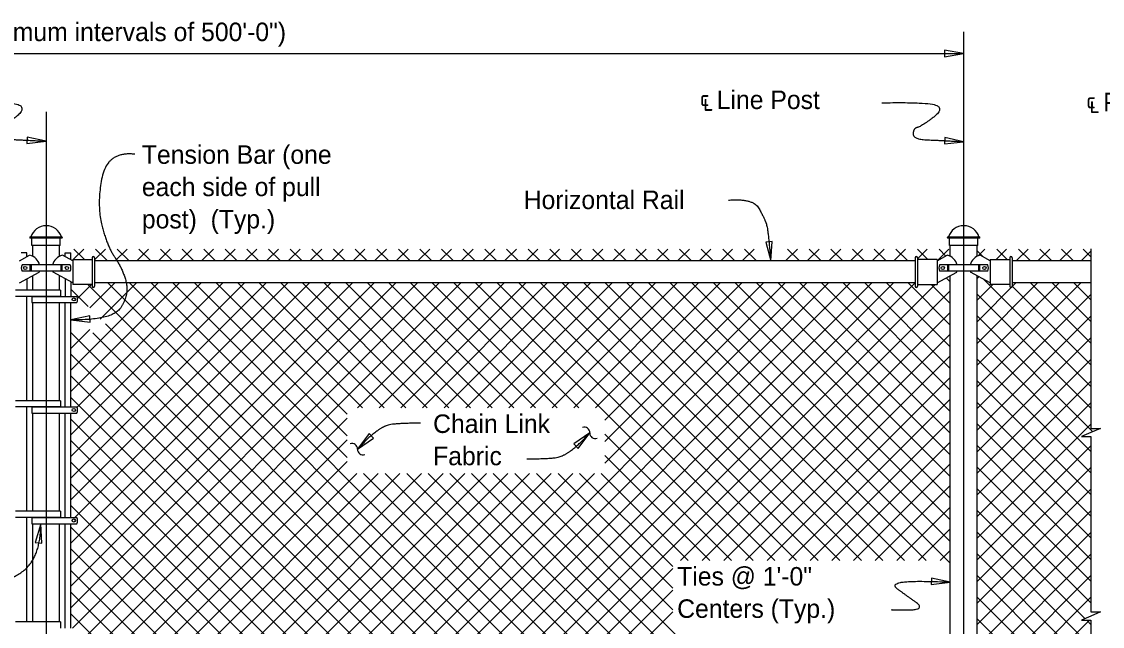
# Model space of a CAD drawing. Extents: x 0.4 to 38.5, y 1.2 to 25.4.
# Drawn here: x 11.81 to 23.59, y 18.85 to 25.44 of the extents above; entities that cross this region are included whole.
import ezdxf

# ---------------------------------------------------------------- set-up
doc = ezdxf.new("R2010")
doc.units = 0
for name, color, linetype in [('CL_Major', 7, 'Continuous'), ('Dimension', 7, 'Continuous'), ('Miscellaneous', 7, 'Continuous'), ('SteelMisc', 7, 'Continuous'), ('TextStructures', 7, 'Continuous')]:
    doc.layers.add(name, color=color, linetype=linetype)

msp = doc.modelspace()

# ---------------------------------------------------------------- linework, layer by layer
at = {"layer": 'CL_Major'}
for p, q in [((22.075, 25.325), (22.075, 16.544)), ((12.075, 24.454), (12.075, 16.544))]:
    msp.add_line(p, q, dxfattribs=at)
at = {"layer": 'Dimension'}
msp.add_line((2.075, 25.088), (22.075, 25.088), dxfattribs=at)
for points in [[(22.075, 25.088), (21.867, 25.124), (21.867, 25.053)], [(12.075, 24.132), (11.869, 24.178), (11.865, 24.108)], [(22.075, 24.127), (21.869, 24.174), (21.865, 24.103)], [(19.972, 22.827), (19.988, 23.038), (19.918, 23.031)], [(12.346, 22.187), (12.555, 22.16), (12.553, 22.23)], [(15.469, 20.777), (15.644, 20.895), (15.595, 20.946)], [(18.001, 20.953), (17.825, 20.835), (17.874, 20.784)], [(12.018, 19.964), (11.957, 19.761), (12.027, 19.753)], [(21.929, 19.328), (21.723, 19.372), (21.72, 19.302)]]:
    msp.add_lwpolyline(points, close=True, dxfattribs=at)
for points in [[(23.462, 22.959), (23.462, 21.003), (23.565, 21.003), (23.462, 20.958), (23.359, 20.913), (23.462, 20.913), (23.462, 20.019)], [(23.462, 20.019), (23.462, 19.002), (23.565, 19.002), (23.462, 18.957), (23.359, 18.912), (23.462, 18.912), (23.462, 16.957)]]:
    msp.add_lwpolyline(points, dxfattribs=at)
for centre, start, end in [((17.941, 20.956), 357.7178, 109.445), ((18.06, 20.951), 177.7178, 289.445), ((15.409, 20.779), 357.7178, 109.445), ((15.529, 20.774), 177.7178, 289.445)]:
    msp.add_arc(centre, 0.0596, start, end, dxfattribs=at)
for points in [[(11.185, 24.556), (11.731, 24.565), (11.854, 24.476), (11.609, 24.295), (11.525, 24.277), (11.525, 24.159), (11.803, 24.147), (12.075, 24.132)], [(21.185, 24.551), (21.731, 24.561), (21.854, 24.472), (21.61, 24.291), (21.525, 24.272), (21.525, 24.154), (21.803, 24.142), (22.075, 24.127)], [(13.041, 23.991), (12.741, 24.023), (12.626, 23.441), (12.741, 22.987), (12.905, 22.752), (12.984, 22.465), (12.797, 22.176), (12.346, 22.187)], [(19.511, 23.49), (19.782, 23.513), (19.908, 23.285), (19.945, 23.164), (19.972, 22.827)], [(16.154, 21.059), (15.864, 21.059), (15.727, 21.014), (15.54, 20.86), (15.502, 20.803)], [(17.315, 20.671), (17.606, 20.671), (17.742, 20.716), (17.929, 20.87), (17.968, 20.927)], [(10.387, 19.368), (10.783, 19.374), (11.232, 19.311), (11.594, 19.294), (12.015, 19.573), (12.018, 19.964)], [(21.297, 19.024), (21.253, 19.024), (21.673, 19.024), (21.423, 19.201), (21.286, 19.303), (21.496, 19.346), (21.929, 19.328)]]:
    msp.add_open_spline(points, degree=2, dxfattribs=at)
at = {"layer": 'Miscellaneous'}
for p, q in [((12.371, 22.843), (12.486, 22.957)), ((12.379, 22.957), (12.493, 22.843)), ((12.604, 22.84), (12.722, 22.957)), ((12.614, 22.957), (12.744, 22.827)), ((12.827, 22.827), (12.957, 22.957)), ((12.85, 22.957), (12.98, 22.827)), ((13.063, 22.827), (13.193, 22.957)), ((13.086, 22.957), (13.216, 22.827)), ((13.299, 22.827), (13.429, 22.957)), ((13.321, 22.957), (13.452, 22.827)), ((13.534, 22.827), (13.665, 22.957)), ((13.557, 22.957), (13.687, 22.827)), ((13.77, 22.827), (13.9, 22.957)), ((13.793, 22.957), (13.923, 22.827)), ((14.006, 22.827), (14.136, 22.957)), ((14.028, 22.957), (14.159, 22.827)), ((14.241, 22.827), (14.372, 22.957)), ((14.264, 22.957), (14.394, 22.827)), ((14.477, 22.827), (14.607, 22.957)), ((14.5, 22.957), (14.63, 22.827)), ((14.713, 22.827), (14.843, 22.957)), ((14.736, 22.957), (14.866, 22.827)), ((14.949, 22.827), (15.079, 22.957)), ((14.971, 22.957), (15.101, 22.827)), ((15.184, 22.827), (15.314, 22.957)), ((15.207, 22.957), (15.337, 22.827)), ((15.42, 22.827), (15.55, 22.957)), ((15.443, 22.957), (15.573, 22.827)), ((15.656, 22.827), (15.786, 22.957)), ((15.678, 22.957), (15.809, 22.827)), ((15.891, 22.827), (16.022, 22.957)), ((15.914, 22.957), (16.044, 22.827)), ((16.127, 22.827), (16.257, 22.957)), ((16.15, 22.957), (16.28, 22.827)), ((16.363, 22.827), (16.493, 22.957)), ((16.386, 22.957), (16.516, 22.827)), ((16.598, 22.827), (16.729, 22.957)), ((16.621, 22.957), (16.751, 22.827)), ((16.834, 22.827), (16.964, 22.957)), ((16.857, 22.957), (16.987, 22.827)), ((17.07, 22.827), (17.2, 22.957)), ((17.093, 22.957), (17.223, 22.827)), ((17.306, 22.827), (17.436, 22.957)), ((17.328, 22.957), (17.458, 22.827)), ((17.541, 22.827), (17.671, 22.957)), ((17.564, 22.957), (17.694, 22.827)), ((17.777, 22.827), (17.907, 22.957)), ((17.8, 22.957), (17.93, 22.827)), ((18.013, 22.827), (18.143, 22.957)), ((18.035, 22.957), (18.166, 22.827)), ((18.248, 22.827), (18.379, 22.957)), ((18.271, 22.957), (18.401, 22.827)), ((18.484, 22.827), (18.614, 22.957)), ((18.507, 22.957), (18.637, 22.827)), ((18.72, 22.827), (18.85, 22.957)), ((18.743, 22.957), (18.873, 22.827)), ((18.956, 22.827), (19.086, 22.957)), ((18.978, 22.957), (19.108, 22.827)), ((19.191, 22.827), (19.321, 22.957)), ((19.214, 22.957), (19.344, 22.827)), ((19.427, 22.827), (19.557, 22.957)), ((19.45, 22.957), (19.58, 22.827)), ((19.663, 22.827), (19.793, 22.957)), ((19.685, 22.957), (19.816, 22.827)), ((20.134, 22.827), (20.264, 22.957)), ((20.157, 22.957), (20.287, 22.827)), ((20.37, 22.827), (20.5, 22.957)), ((20.392, 22.957), (20.523, 22.827)), ((20.605, 22.827), (20.736, 22.957)), ((20.628, 22.957), (20.758, 22.827)), ((20.841, 22.827), (20.971, 22.957)), ((20.864, 22.957), (20.994, 22.827)), ((21.077, 22.827), (21.207, 22.957)), ((21.1, 22.957), (21.23, 22.827)), ((21.313, 22.827), (21.443, 22.957)), ((21.335, 22.957), (21.465, 22.827)), ((21.571, 22.957), (21.686, 22.843)), ((21.572, 22.851), (21.678, 22.957)), ((21.785, 22.829), (21.914, 22.957)), ((21.807, 22.957), (21.882, 22.881)), ((22.221, 22.936), (22.286, 22.871)), ((22.233, 22.883), (22.307, 22.957)), ((22.428, 22.843), (22.543, 22.957)), ((22.436, 22.957), (22.55, 22.843)), ((22.649, 22.827), (22.779, 22.957)), ((22.671, 22.957), (22.802, 22.827)), ((22.884, 22.827), (23.015, 22.957)), ((22.907, 22.957), (23.037, 22.827)), ((23.12, 22.827), (23.25, 22.957)), ((23.143, 22.957), (23.273, 22.827)), ((23.356, 22.827), (23.462, 22.933)), ((23.379, 22.957), (23.462, 22.874)), ((21.885, 22.643), (21.929, 22.599)), ((22.221, 22.635), (22.242, 22.656)), ((22.294, 22.627), (23.462, 21.46)), ((12.346, 19.517), (15.416, 22.588)), ((12.346, 19.046), (15.888, 22.588)), ((12.346, 20.932), (14.002, 22.588)), ((12.346, 20.46), (14.473, 22.588)), ((12.346, 21.403), (13.53, 22.588)), ((12.346, 19.282), (15.652, 22.588)), ((12.346, 19.753), (15.18, 22.588)), ((12.346, 20.224), (14.709, 22.588)), ((12.346, 20.696), (14.238, 22.588)), ((12.346, 18.339), (16.595, 22.588)), ((12.346, 18.574), (16.359, 22.588)), ((12.346, 21.639), (13.295, 22.588)), ((12.346, 22.519), (12.534, 22.33)), ((12.362, 18.826), (16.123, 22.588)), ((12.389, 20.031), (14.945, 22.588)), ((12.412, 21.233), (13.766, 22.588)), ((12.418, 22.418), (12.578, 22.577)), ((12.53, 22.57), (17.69, 17.41)), ((12.552, 22.317), (12.823, 22.588)), ((12.663, 22.192), (13.059, 22.588)), ((12.748, 22.588), (17.925, 17.41)), ((12.984, 22.588), (18.161, 17.41)), ((13.22, 22.588), (18.397, 17.41)), ((13.455, 22.588), (15.358, 20.685)), ((13.691, 22.588), (15.358, 20.921)), ((13.927, 22.588), (15.358, 21.157)), ((14.163, 22.588), (15.523, 21.227)), ((14.398, 22.588), (15.759, 21.227)), ((14.634, 22.588), (15.994, 21.227)), ((14.87, 22.588), (16.23, 21.227)), ((15.105, 22.588), (16.466, 21.227)), ((15.189, 17.41), (20.366, 22.588)), ((15.341, 22.588), (16.702, 21.227)), ((15.424, 17.41), (20.602, 22.588)), ((15.47, 21.227), (16.83, 22.588)), ((15.577, 22.588), (16.937, 21.227)), ((15.66, 17.41), (20.837, 22.588)), ((15.706, 21.227), (17.066, 22.588)), ((15.812, 22.588), (17.173, 21.227)), ((15.896, 17.41), (21.073, 22.588)), ((15.941, 21.227), (17.302, 22.588)), ((16.048, 22.588), (17.409, 21.227)), ((16.132, 17.41), (21.309, 22.588)), ((16.177, 21.227), (17.537, 22.588)), ((16.284, 22.588), (17.644, 21.227)), ((16.367, 17.41), (21.546, 22.589)), ((16.413, 21.227), (17.773, 22.588)), ((16.52, 22.588), (17.88, 21.227)), ((16.603, 17.41), (21.763, 22.57)), ((16.648, 21.227), (18.009, 22.588)), ((16.755, 22.588), (19.781, 19.562)), ((16.884, 21.227), (18.245, 22.588)), ((16.991, 22.588), (20.017, 19.562)), ((17.12, 21.227), (18.48, 22.588)), ((17.227, 22.588), (20.253, 19.562)), ((17.355, 21.227), (18.716, 22.588)), ((17.462, 22.588), (20.488, 19.562)), ((17.591, 21.227), (18.952, 22.588)), ((17.698, 22.588), (20.724, 19.562)), ((17.827, 21.227), (19.187, 22.588)), ((17.934, 22.588), (20.96, 19.562)), ((18.063, 21.227), (19.423, 22.588)), ((18.166, 21.094), (19.659, 22.588)), ((18.166, 20.623), (20.13, 22.588)), ((18.166, 20.859), (19.894, 22.588)), ((18.169, 22.588), (21.195, 19.562)), ((18.405, 22.588), (21.431, 19.562)), ((18.641, 22.588), (21.667, 19.562)), ((18.877, 22.588), (21.929, 19.535)), ((18.99, 19.562), (21.929, 22.501)), ((19.112, 22.588), (21.929, 19.771)), ((19.348, 22.588), (21.929, 20.006)), ((19.584, 22.588), (21.929, 20.242)), ((19.819, 22.588), (21.929, 20.478)), ((20.055, 22.588), (21.929, 20.713)), ((20.291, 22.588), (21.929, 20.949)), ((20.526, 22.588), (21.929, 21.185)), ((20.762, 22.588), (21.929, 21.42)), ((20.998, 22.588), (21.929, 21.656)), ((21.234, 22.588), (21.929, 21.892)), ((21.469, 22.588), (21.929, 22.128)), ((21.722, 22.57), (21.929, 22.363)), ((22.221, 21.456), (23.352, 22.588)), ((22.221, 21.692), (23.116, 22.588)), ((22.221, 22.164), (22.645, 22.588)), ((22.221, 22.399), (22.392, 22.57)), ((22.225, 21.932), (22.881, 22.588)), ((22.604, 22.553), (23.462, 21.695)), ((22.805, 22.588), (23.462, 21.931)), ((23.041, 22.588), (23.462, 22.167)), ((23.277, 22.588), (23.462, 22.402)), ((22.221, 22.465), (23.462, 21.224)), ((22.221, 21.221), (23.462, 22.462)), ((19.226, 19.562), (21.929, 22.265)), ((22.221, 22.229), (23.483, 20.967)), ((22.221, 20.985), (23.462, 22.226)), ((12.346, 21.874), (12.553, 22.081)), ((12.346, 22.047), (16.983, 17.41)), ((12.586, 22.043), (17.218, 17.41)), ((12.722, 22.142), (17.454, 17.41)), ((19.461, 19.562), (21.929, 22.03)), ((22.221, 21.994), (23.462, 20.752)), ((22.221, 20.749), (23.462, 21.99)), ((12.346, 21.811), (16.747, 17.41)), ((19.697, 19.562), (21.929, 21.794)), ((22.221, 21.758), (23.462, 20.517)), ((22.221, 20.514), (23.462, 21.755)), ((12.346, 21.576), (16.511, 17.41)), ((19.933, 19.562), (21.929, 21.558)), ((22.221, 21.522), (23.462, 20.281)), ((22.221, 20.278), (23.462, 21.519)), ((12.346, 21.34), (16.276, 17.41)), ((20.168, 19.562), (21.929, 21.322)), ((22.221, 21.286), (23.462, 20.045)), ((22.221, 20.042), (23.462, 21.283)), ((12.346, 18.103), (15.358, 21.115)), ((12.346, 21.104), (16.04, 17.41)), ((20.404, 19.562), (21.929, 21.087)), ((22.221, 21.051), (23.462, 19.81)), ((22.221, 19.807), (23.462, 21.048)), ((12.346, 17.867), (15.358, 20.879)), ((12.346, 20.869), (15.804, 17.41)), ((18.166, 20.941), (19.545, 19.562)), ((20.64, 19.562), (21.929, 20.851)), ((22.221, 20.815), (23.462, 19.574)), ((22.221, 19.571), (23.462, 20.812)), ((12.346, 17.632), (15.358, 20.643)), ((12.346, 20.633), (15.568, 17.41)), ((18.166, 20.706), (19.31, 19.562)), ((20.875, 19.562), (21.929, 20.615)), ((12.376, 17.426), (15.46, 20.51)), ((12.604, 17.419), (15.695, 20.51)), ((12.832, 17.41), (15.931, 20.51)), ((13.067, 17.41), (16.167, 20.51)), ((13.303, 17.41), (16.402, 20.51)), ((13.539, 17.41), (16.638, 20.51)), ((13.774, 17.41), (16.874, 20.51)), ((14.01, 17.41), (17.109, 20.51)), ((14.246, 17.41), (17.345, 20.51)), ((14.482, 17.41), (17.581, 20.51)), ((14.717, 17.41), (17.817, 20.51)), ((14.953, 17.41), (18.052, 20.51)), ((15.533, 20.51), (18.633, 17.41)), ((15.769, 20.51), (18.868, 17.41)), ((16.005, 20.51), (19.104, 17.41)), ((16.24, 20.51), (19.34, 17.41)), ((16.476, 20.51), (19.575, 17.41)), ((16.712, 20.51), (19.811, 17.41)), ((16.948, 20.51), (20.047, 17.41)), ((17.183, 20.51), (20.282, 17.41)), ((17.419, 20.51), (18.904, 19.024)), ((17.655, 20.51), (18.904, 19.26)), ((17.89, 20.51), (18.904, 19.496)), ((18.126, 20.51), (19.074, 19.562)), ((22.221, 20.579), (23.462, 19.338)), ((22.221, 19.335), (23.462, 20.576)), ((12.346, 20.397), (15.333, 17.41)), ((21.111, 19.562), (21.929, 20.38)), ((22.221, 20.344), (23.462, 19.103)), ((22.221, 19.099), (23.462, 20.341)), ((12.346, 20.162), (15.097, 17.41)), ((21.347, 19.562), (21.929, 20.144)), ((22.221, 20.108), (23.399, 18.929)), ((22.221, 18.864), (23.462, 20.105)), ((12.346, 19.926), (14.861, 17.41)), ((21.583, 19.562), (21.929, 19.908)), ((22.221, 19.872), (23.462, 18.631)), ((22.221, 18.628), (23.462, 19.869)), ((12.346, 19.69), (14.626, 17.41)), ((21.818, 19.562), (21.929, 19.673)), ((22.221, 19.637), (23.462, 18.395)), ((22.221, 18.392), (23.462, 19.633)), ((12.346, 19.454), (14.39, 17.41)), ((16.839, 17.41), (18.904, 19.476)), ((22.221, 19.401), (23.462, 18.16)), ((22.221, 18.157), (23.462, 19.398)), ((12.346, 19.219), (14.154, 17.41)), ((17.074, 17.41), (18.904, 19.24)), ((22.221, 19.165), (23.462, 17.924)), ((22.221, 17.921), (23.462, 19.162)), ((12.346, 18.983), (13.919, 17.41)), ((17.31, 17.41), (18.904, 19.005)), ((22.221, 18.929), (23.462, 17.688)), ((22.221, 17.685), (23.447, 18.912)), ((23.417, 18.912), (23.462, 18.867))]:
    msp.add_line(p, q, dxfattribs=at)
at = {"layer": 'SteelMisc'}
for p, q in [((11.903, 23.089), (12.247, 23.089)), ((21.903, 23.089), (22.247, 23.089)), ((12.247, 23.077), (11.903, 23.077)), ((11.921, 22.997), (11.921, 23.077)), ((12.229, 22.997), (11.921, 22.997)), ((11.929, 22.877), (11.929, 22.997)), ((12.221, 22.877), (12.221, 22.997)), ((12.229, 22.997), (12.229, 23.077)), ((22.247, 23.077), (21.903, 23.077)), ((21.921, 22.997), (21.921, 23.077)), ((22.229, 22.997), (21.921, 22.997)), ((21.929, 22.877), (21.929, 22.997)), ((22.221, 22.877), (22.221, 22.997)), ((22.229, 22.997), (22.229, 23.077)), ((11.785, 22.828), (11.896, 22.889)), ((11.867, 22.916), (11.804, 22.916)), ((11.867, 22.873), (11.867, 22.916)), ((12.365, 22.828), (12.254, 22.889)), ((12.283, 22.874), (12.283, 22.916)), ((12.283, 22.916), (12.346, 22.916)), ((12.346, 22.838), (12.346, 22.916)), ((12.578, 22.862), (12.578, 22.552)), ((12.604, 22.862), (12.604, 22.552)), ((21.546, 22.862), (21.546, 22.552)), ((21.572, 22.862), (21.572, 22.552)), ((21.785, 22.828), (21.896, 22.889)), ((22.365, 22.828), (22.254, 22.889)), ((22.578, 22.862), (22.578, 22.552)), ((22.604, 22.862), (22.604, 22.552)), ((12.337, 22.785), (11.813, 22.785)), ((11.895, 22.777), (11.918, 22.777)), ((11.895, 22.768), (11.918, 22.768)), ((11.895, 22.757), (11.918, 22.757)), ((11.895, 22.745), (11.918, 22.745)), ((11.895, 22.733), (11.918, 22.733)), ((12.255, 22.777), (12.232, 22.777)), ((12.255, 22.768), (12.232, 22.768)), ((12.255, 22.757), (12.232, 22.757)), ((12.255, 22.745), (12.232, 22.745)), ((12.255, 22.733), (12.232, 22.733)), ((12.365, 22.843), (12.365, 22.57)), ((12.365, 22.843), (12.578, 22.843)), ((21.546, 22.827), (12.604, 22.827)), ((21.785, 22.843), (21.572, 22.843)), ((21.785, 22.843), (21.785, 22.57)), ((22.337, 22.785), (21.813, 22.785)), ((21.895, 22.777), (21.918, 22.777)), ((21.895, 22.768), (21.918, 22.768)), ((21.895, 22.757), (21.918, 22.757)), ((21.895, 22.745), (21.918, 22.745)), ((21.895, 22.733), (21.918, 22.733)), ((22.255, 22.777), (22.232, 22.777)), ((22.255, 22.768), (22.232, 22.768)), ((22.255, 22.757), (22.232, 22.757)), ((22.255, 22.745), (22.232, 22.745)), ((22.255, 22.733), (22.232, 22.733)), ((22.365, 22.843), (22.365, 22.57)), ((22.365, 22.843), (22.578, 22.843)), ((23.462, 22.827), (22.604, 22.827)), ((11.785, 22.588), (11.999, 22.707)), ((12.337, 22.717), (11.813, 22.717)), ((11.867, 22.633), (11.867, 22.508)), ((11.895, 22.724), (11.918, 22.724)), ((11.929, 22.508), (11.929, 22.668)), ((12.365, 22.588), (12.151, 22.707)), ((12.221, 22.508), (12.221, 22.668)), ((12.255, 22.724), (12.232, 22.724)), ((12.283, 22.633), (12.283, 22.441)), ((12.283, 22.633), (12.283, 22.586)), ((21.785, 22.588), (21.999, 22.707)), ((22.337, 22.717), (21.813, 22.717)), ((21.895, 22.724), (21.918, 22.724)), ((21.929, 17.461), (21.929, 22.668)), ((22.365, 22.588), (22.151, 22.707)), ((22.221, 17.461), (22.221, 22.668)), ((22.255, 22.724), (22.232, 22.724)), ((12.231, 22.508), (11.74, 22.508)), ((12.231, 22.508), (12.231, 22.441)), ((12.346, 22.599), (12.346, 22.441)), ((12.346, 22.599), (12.346, 22.586)), ((12.578, 22.57), (12.365, 22.57)), ((21.546, 22.588), (12.604, 22.588)), ((21.572, 22.57), (21.785, 22.57)), ((22.578, 22.57), (22.365, 22.57)), ((23.462, 22.588), (22.604, 22.588)), ((12.231, 22.441), (11.74, 22.441)), ((11.867, 21.304), (11.867, 22.441)), ((11.919, 22.441), (11.919, 22.373)), ((11.919, 22.441), (12.41, 22.441)), ((11.919, 22.373), (12.41, 22.373)), ((11.929, 21.304), (11.929, 22.373)), ((12.221, 21.304), (12.221, 22.373)), ((12.283, 21.236), (12.283, 22.373)), ((12.346, 21.236), (12.346, 22.373)), ((12.231, 21.304), (11.74, 21.304)), ((12.231, 21.236), (11.74, 21.236)), ((11.867, 20.099), (11.867, 21.236)), ((11.919, 21.236), (11.919, 21.168)), ((11.919, 21.236), (12.41, 21.236)), ((12.231, 21.304), (12.231, 21.236)), ((11.919, 21.168), (12.41, 21.168)), ((11.929, 20.099), (11.929, 21.168)), ((12.221, 20.099), (12.221, 21.168)), ((12.283, 20.031), (12.283, 21.168)), ((12.346, 20.031), (12.346, 21.168)), ((12.231, 20.099), (11.74, 20.099)), ((12.231, 20.031), (11.74, 20.031)), ((11.867, 18.894), (11.867, 20.031)), ((11.919, 20.031), (11.919, 19.964)), ((11.919, 20.031), (12.41, 20.031)), ((12.231, 20.099), (12.231, 20.031)), ((11.919, 19.964), (12.41, 19.964)), ((11.929, 18.894), (11.929, 19.964)), ((12.221, 18.894), (12.221, 19.964)), ((12.283, 18.826), (12.283, 19.964)), ((12.346, 18.826), (12.346, 19.964)), ((12.231, 18.894), (11.74, 18.894)), ((12.231, 18.894), (12.231, 18.826))]:
    msp.add_line(p, q, dxfattribs=at)
for centre, radius, start, end in [((11.903, 23.083), 0.00613, 91.1647, 268.8353), ((12.247, 23.083), 0.00613, 271.1647, 88.8353), ((21.903, 23.083), 0.00613, 91.1647, 268.8353), ((22.247, 23.083), 0.00613, 271.1647, 88.8353), ((12.591, 22.862), 0.0134, 0, 180), ((21.559, 22.862), 0.0134, 0, 180), ((22.591, 22.862), 0.0134, 0, 180), ((12.591, 22.552), 0.0134, 180, 0), ((21.559, 22.552), 0.0134, 180, 0), ((22.591, 22.552), 0.0134, 180, 0)]:
    msp.add_arc(centre, radius, start, end, dxfattribs=at)
for centre, major_axis, start_param, end_param in [((12.076, 23.048), (0.171, 0), 0.252602, 2.888574), ((22.076, 23.048), (0.171, 0), 0.252602, 2.888574), ((11.862, 22.753), (0.146, 0), 0.231126, 1.331255), ((12.288, 22.753), (-0.146, 0), 4.95193, 6.05206), ((21.862, 22.753), (0.146, 0), 0.231126, 1.331255), ((22.288, 22.753), (-0.146, 0), 4.95193, 6.05206), ((11.882, 22.751), (-0.0776, 0), 5.810211, 6.75616), ((12.268, 22.751), (0.0776, 0), 5.810211, 6.75616), ((21.882, 22.751), (-0.0776, 0), 5.810211, 6.75616), ((22.268, 22.751), (0.0776, 0), 5.810211, 6.75616), ((11.862, 22.753), (0.146, 0), 5.947976, 6.024627), ((12.288, 22.753), (-0.146, 0), 0.258558, 0.335209), ((21.862, 22.753), (0.146, 0), 5.947976, 6.024627), ((22.288, 22.753), (-0.146, 0), 0.258558, 0.335209), ((12.341, 22.408), (0.0776, 0), 5.801244, 6.745158), ((12.341, 21.203), (0.0776, 0), 5.801046, 6.744962), ((12.341, 21.203), (0.0776, 0), 5.801046, 6.744962), ((12.341, 19.998), (0.0776, 0), 5.800848, 6.744767), ((12.341, 19.998), (0.0776, 0), 5.800848, 6.744767)]:
    msp.add_ellipse(centre, major_axis=major_axis, ratio=0.957868, start_param=start_param, end_param=end_param, dxfattribs=at)
for centre, major_axis in [((11.848, 22.751), (0.0178, 0)), ((12.302, 22.751), (-0.0178, 0)), ((21.848, 22.751), (0.0178, 0)), ((22.302, 22.751), (-0.0178, 0)), ((12.377, 22.408), (-0.0177, 0)), ((12.377, 21.203), (-0.0177, 0)), ((12.377, 21.203), (-0.0177, 0)), ((12.377, 19.999), (-0.0177, 0)), ((12.377, 19.999), (-0.0177, 0))]:
    msp.add_ellipse(centre, major_axis=major_axis, ratio=0.957868, dxfattribs=at)

# ---------------------------------------------------------------- texts
at = {"layer": 'Dimension'}
for s, p in [('Tension Bar (one ', (13.119, 23.886)), ('each side of pull ', (13.119, 23.534)), ('post)  (Typ.)', (13.119, 23.182)), ('Chain Link ', (16.293, 20.953)), ('Fabric ', (16.293, 20.601)), ('Ties @ 1\'-0" ', (18.953, 19.29)), ('Centers (Typ.)', (18.953, 18.938))]:
    msp.add_text(s, height=0.2016, dxfattribs=at).set_placement(p)
at = {"layer": 'TextStructures'}
for s, p in [('Pull Post Assembly (required at maximum intervals of 500\'-0")', (7.307, 25.223)), ('℄ Line Post', (19.2, 24.483)), ('℄ Pull Post', (23.411, 24.459)), ('Horizontal Rail', (17.28, 23.393))]:
    msp.add_text(s, height=0.2016, dxfattribs=at).set_placement(p)

doc.saveas('drawing.dxf')
